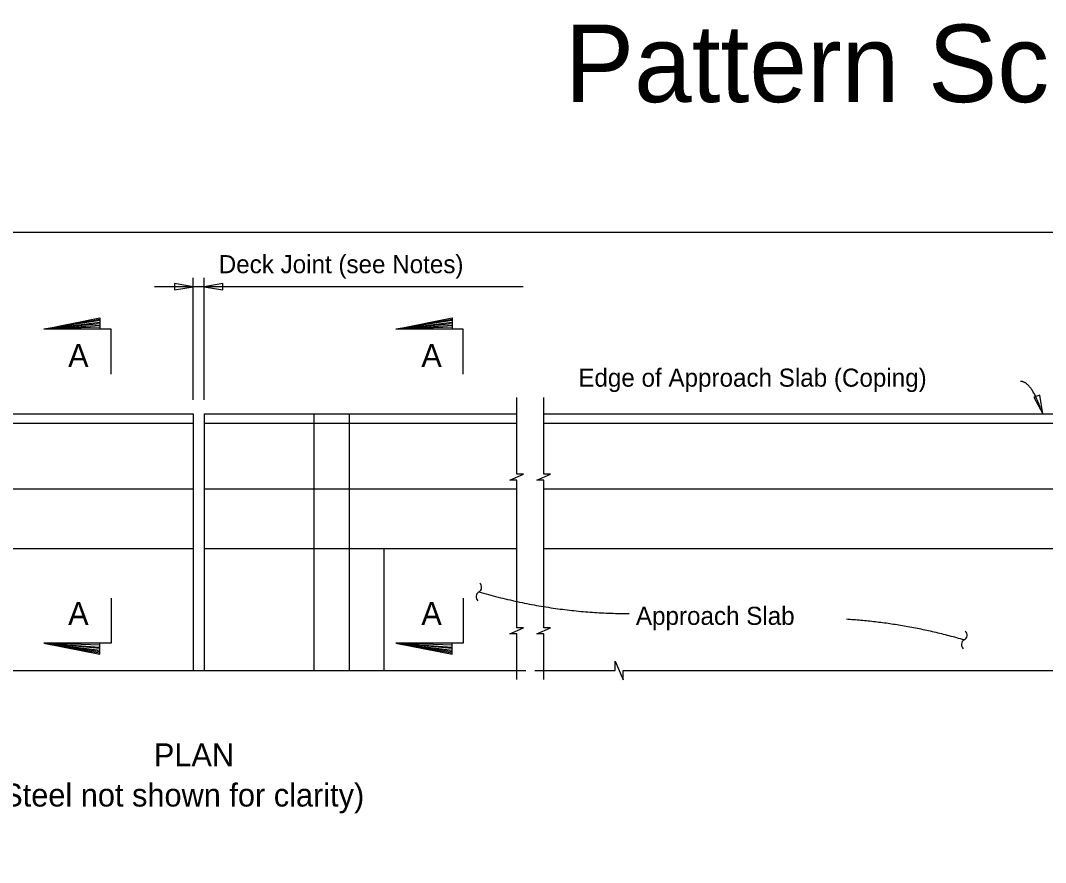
# Model space of a CAD drawing. Extents: x 130649.2 to 130733.9, y 88659.3 to 88705.5.
# Drawn here: x 130667.25 to 130678.67, y 88695.12 to 88704.51 of the extents above; entities that cross this region are included whole.
import ezdxf

# ---------------------------------------------------------------- set-up
doc = ezdxf.new("R2010")
doc.units = 0
for name, color, linetype in [('ActivePts-ConstElements', 7, 'Continuous'), ('AdhocPoint_dp', 7, 'Continuous'), ('Patterning', 7, 'Continuous'), ('PlotBorder_dp', 7, 'Continuous')]:
    doc.layers.add(name, color=color, linetype=linetype)

msp = doc.modelspace()

# ---------------------------------------------------------------- linework, layer by layer
at = {"layer": 'ActivePts-ConstElements'}
msp.add_lwpolyline([(130649.241, 88676.196), (130690.292, 88676.196), (130690.292, 88702.143), (130649.241, 88702.143)], close=True, dxfattribs=at)
at = {"layer": 'AdhocPoint_dp'}
for p, q in [((130661.172, 88700.12), (130669.172, 88700.12)), ((130669.172, 88700.12), (130669.172, 88697.26)), ((130669.294, 88700.12), (130669.294, 88697.26)), ((130669.294, 88700.12), (130672.778, 88700.12)), ((130670.514, 88700.12), (130670.514, 88697.26)), ((130670.911, 88700.12), (130670.911, 88697.26)), ((130673.078, 88700.12), (130689.059, 88700.12)), ((130661.172, 88700.016), (130669.172, 88700.016)), ((130669.294, 88700.016), (130672.778, 88700.016)), ((130673.078, 88700.016), (130682.393, 88700.016)), ((130661.172, 88699.287), (130669.172, 88699.287)), ((130669.294, 88699.287), (130672.778, 88699.287)), ((130673.078, 88699.287), (130682.393, 88699.287)), ((130661.172, 88698.62), (130669.172, 88698.62)), ((130669.294, 88698.62), (130672.778, 88698.62)), ((130671.294, 88698.62), (130671.294, 88697.26)), ((130673.078, 88698.62), (130686.059, 88698.62))]:
    msp.add_line(p, q, dxfattribs=at)
at = {"layer": 'PlotBorder_dp'}
for p, q in [((130669.172, 88700.279), (130669.172, 88701.639)), ((130669.294, 88700.279), (130669.294, 88701.639)), ((130672.846, 88701.538), (130668.74, 88701.538)), ((130667.508, 88701.065), (130668.133, 88701.175)), ((130668.133, 88701.161), (130667.508, 88701.065)), ((130667.508, 88701.065), (130668.133, 88701.145)), ((130668.133, 88701.126), (130667.508, 88701.065)), ((130667.508, 88701.065), (130668.133, 88701.108)), ((130671.43, 88701.065), (130672.055, 88701.175)), ((130672.055, 88701.161), (130671.43, 88701.065)), ((130671.43, 88701.065), (130672.055, 88701.145)), ((130672.055, 88701.126), (130671.43, 88701.065)), ((130671.43, 88701.065), (130672.055, 88701.108)), ((130668.133, 88701.088), (130667.508, 88701.065)), ((130672.055, 88701.088), (130671.43, 88701.065)), ((130668.133, 88697.542), (130667.508, 88697.566)), ((130667.508, 88697.566), (130668.133, 88697.522)), ((130668.133, 88697.504), (130667.508, 88697.566)), ((130667.508, 88697.566), (130668.133, 88697.486)), ((130668.133, 88697.469), (130667.508, 88697.566)), ((130667.508, 88697.566), (130668.133, 88697.456)), ((130672.055, 88697.542), (130671.43, 88697.566)), ((130671.43, 88697.566), (130672.055, 88697.522)), ((130672.055, 88697.504), (130671.43, 88697.566)), ((130671.43, 88697.566), (130672.055, 88697.486)), ((130672.055, 88697.469), (130671.43, 88697.566)), ((130671.43, 88697.566), (130672.055, 88697.456))]:
    msp.add_line(p, q, dxfattribs=at)
for points in [[(130669.172, 88701.538), (130668.963, 88701.573), (130668.963, 88701.503)], [(130669.294, 88701.538), (130669.502, 88701.503), (130669.502, 88701.573)], [(130678.636, 88700.12), (130678.603, 88700.329), (130678.536, 88700.306)]]:
    msp.add_lwpolyline(points, close=True, dxfattribs=at)
for points in [[(130668.258, 88700.565), (130668.258, 88701.065), (130667.508, 88701.065), (130668.133, 88701.19), (130668.133, 88701.065)], [(130672.18, 88700.565), (130672.18, 88701.065), (130671.43, 88701.065), (130672.055, 88701.19), (130672.055, 88701.065)], [(130672.778, 88698.336), (130672.778, 88699.382), (130672.701, 88699.382), (130672.851, 88699.449), (130672.778, 88699.449), (130672.778, 88700.304)], [(130673.078, 88698.336), (130673.078, 88699.382), (130673.001, 88699.382), (130673.151, 88699.449), (130673.078, 88699.449), (130673.078, 88700.304)], [(130672.778, 88697.16), (130672.778, 88697.669), (130672.701, 88697.669), (130672.851, 88697.735), (130672.778, 88697.735), (130672.778, 88698.336)], [(130673.078, 88697.16), (130673.078, 88697.669), (130673.001, 88697.669), (130673.151, 88697.735), (130673.078, 88697.735), (130673.078, 88698.336)], [(130668.258, 88698.066), (130668.258, 88697.566), (130667.508, 88697.566), (130668.133, 88697.441), (130668.133, 88697.566)], [(130672.18, 88698.066), (130672.18, 88697.566), (130671.43, 88697.566), (130672.055, 88697.441), (130672.055, 88697.566)], [(130661.099, 88697.26), (130663.647, 88697.26), (130663.647, 88697.363), (130663.692, 88697.26), (130663.737, 88697.157), (130663.737, 88697.26), (130669.172, 88697.26)], [(130672.978, 88697.26), (130673.871, 88697.26), (130673.871, 88697.363), (130673.916, 88697.26), (130673.961, 88697.157), (130673.961, 88697.26), (130679.851, 88697.26)], [(130669.172, 88697.26), (130672.878, 88697.26)]]:
    msp.add_lwpolyline(points, dxfattribs=at)
for centre, start, end in [((130672.382, 88698.083), 118.0989, 229.8261), ((130672.326, 88698.188), 298.0989, 49.8261), ((130677.734, 88697.654), 298.0989, 49.8261), ((130677.79, 88697.549), 118.0989, 229.8261)]:
    msp.add_arc(centre, 0.0596, start, end, dxfattribs=at)
for points in [[(130678.636, 88700.12), (130678.513, 88700.483), (130678.39, 88700.483)], [(130672.354, 88698.136), (130673.192, 88697.895), (130674.029, 88697.895)], [(130677.762, 88697.601), (130677.106, 88697.79), (130676.45, 88697.831)]]:
    msp.add_open_spline(points, degree=2, dxfattribs=at)

# ---------------------------------------------------------------- texts
at = {"layer": 'Patterning'}
for s, height, p in [('Pattern Scale (PS) = ', 0.864, (130673.313, 88703.596)), ('Deck Joint (see Notes)', 0.2016, (130669.456, 88701.689)), ('Edge of Approach Slab (Coping)', 0.2016, (130673.462, 88700.424)), ('Approach Slab', 0.2016, (130674.104, 88697.769))]:
    msp.add_text(s, height=height, dxfattribs=at).set_placement(p)
for p in [(130667.778, 88700.643), (130671.713, 88700.643), (130667.778, 88697.768), (130671.713, 88697.768)]:
    msp.add_text('A', height=0.256, rotation=360, dxfattribs=at).set_placement(p)
at = {"layer": 'PlotBorder_dp'}
for s, p in [('PLAN', (130668.733, 88696.192)), ('(Reinforcing Steel not shown for clarity)', (130665.103, 88695.744))]:
    msp.add_text(s, height=0.256, dxfattribs=at).set_placement(p)

doc.saveas('drawing.dxf')
